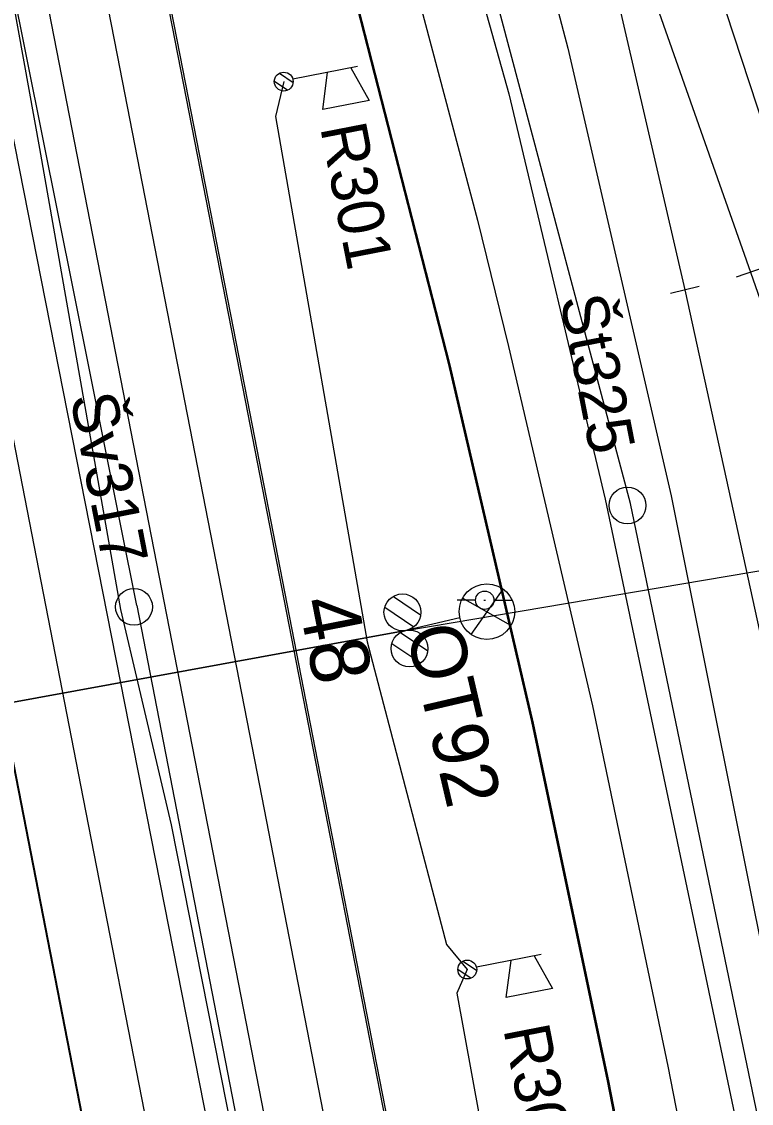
# Model space of a CAD drawing. Extents: x -545736 to -544888, y -1122892 to -1119128.
# Drawn here: x -545228.83 to -545209.03, y -1121674.47 to -1121645.11 of the extents above; entities that cross this region are included whole.
import ezdxf

# ---------------------------------------------------------------- set-up
doc = ezdxf.new("R2010")
doc.units = 0
for name, color, linetype in [('Podbarveni_Nastupiste', 7, 'Continuous'), ('Vrstva 1 - Koleje', 7, 'Continuous'), ('Vrstva 11 - Trakce', 7, 'Continuous'), ('Vrstva 14_zastreseni a nastupiste', 7, 'Continuous'), ('Vrstva 16_plochy', 7, 'Continuous'), ('Vrstva 2 - Vyhybky', 7, 'Continuous'), ('Vrstva 25', 7, 'Continuous'), ('Vrstva 28 - zabzar', 7, 'Continuous'), ('Vrstva 31', 7, 'Continuous'), ('Vrstva 33 - prvky sdelzar', 7, 'Continuous'), ('Vrstva 4 - Teren - stezky - prechody - plochy', 7, 'Continuous'), ('Vrstva 41', 7, 'Continuous'), ('Vrstva 43', 7, 'Continuous'), ('Vrstva 44', 7, 'Continuous')]:
    doc.layers.add(name, color=color, linetype=linetype)

msp = doc.modelspace()

# ---------------------------------------------------------------- linework, layer by layer
at = {"layer": 'Podbarveni_Nastupiste'}
for points in [[(-545223.443, -1121694.09), (-545224.969, -1121686.265), (-545226.877, -1121676.484), (-545228.786, -1121666.678), (-545230.697, -1121656.879), (-545232.606, -1121647.081), (-545234.517, -1121637.287), (-545236.429, -1121627.481), (-545237.19, -1121623.577)], [(-545209.127, -1121693.444), (-545211.033, -1121683.652), (-545212.936, -1121673.863), (-545214.985, -1121664.112), (-545217.251, -1121654.384), (-545219.728, -1121644.713), (-545222.418, -1121635.111), (-545225.09, -1121625.931)], [(-545228.364, -1121626.398), (-545228.067, -1121627.952), (-545226.537, -1121635.795), (-545224.621, -1121645.607), (-545222.714, -1121655.377), (-545220.803, -1121665.19), (-545219.276, -1121673.043), (-545217.368, -1121682.822), (-545215.446, -1121692.657)]]:
    msp.add_lwpolyline(points, dxfattribs=at)
at = {"layer": 'Vrstva 1 - Koleje'}
for points in [[(-545253.234, -1121532.442), (-545253.081, -1121533.227), (-545252.417, -1121536.637), (-545250.056, -1121548.75), (-545246.877, -1121565.063), (-545245.498, -1121572.114), (-545243.946, -1121580.081), (-545242.319, -1121588.422), (-545241.158, -1121594.375), (-545240.981, -1121595.287), (-545240.164, -1121599.483), (-545238.848, -1121606.232), (-545237.423, -1121613.54), (-545235.54, -1121623.195), (-545234.061, -1121630.792), (-545232.534, -1121638.617), (-545230.963, -1121646.68), (-545229.074, -1121656.39), (-545227.16, -1121666.203), (-545225.219, -1121676.178), (-545223.305, -1121685.999), (-545221.784, -1121693.786)], [(-545248.408, -1121532.36), (-545248.259, -1121533.126), (-545247.475, -1121537.15), (-545244.429, -1121552.772), (-545240.225, -1121574.335), (-545238.879, -1121581.23), (-545237.501, -1121588.285), (-545235.953, -1121596.229), (-545234.349, -1121604.465), (-545232.932, -1121611.716), (-545232.152, -1121615.725), (-545231.632, -1121618.395), (-545230.091, -1121626.302), (-545228.735, -1121633.259), (-545226.244, -1121646.023), (-545224.344, -1121655.776), (-545222.446, -1121665.521), (-545220.908, -1121673.435), (-545219.01, -1121683.169), (-545217.101, -1121692.961)], [(-545225.616, -1121618.075), (-545225.108, -1121619.818), (-545223.546, -1121625.178), (-545221.373, -1121632.649), (-545218.975, -1121641.029), (-545216.466, -1121650.504), (-545215.616, -1121653.926), (-545213.339, -1121663.68), (-545211.292, -1121673.464), (-545209.393, -1121683.199), (-545207.488, -1121692.987)], [(-545219.417, -1121620.337), (-545219.184, -1121621.102), (-545214.573, -1121636.23), (-545210.836, -1121652.388), (-545208.739, -1121661.984), (-545207.134, -1121670.028), (-545205.963, -1121676.033), (-545204.911, -1121681.437), (-545204.598, -1121683.045), (-545202.446, -1121694.084)], [(-545219.417, -1121620.337), (-545219.184, -1121621.102), (-545214.573, -1121636.23), (-545209.054, -1121651.908), (-545206.51, -1121659.176), (-545203.144, -1121668.78), (-545201.044, -1121674.823), (-545198.261, -1121683.246), (-545197.623, -1121685.281), (-545196.328, -1121689.408), (-545194.686, -1121694.87)]]:
    msp.add_lwpolyline(points, dxfattribs=at)
at = {"layer": 'Vrstva 11 - Trakce'}
for p, q in [((-545218.746, -1121660.712), (-545218.005, -1121661.209)), ((-545218.977, -1121661.008), (-545218.19, -1121661.537)), ((-545218.555, -1121661.696), (-545217.812, -1121662.194)), ((-545218.785, -1121661.994), (-545217.999, -1121662.52))]:
    msp.add_line(p, q, dxfattribs=at)
msp.add_lwpolyline([(-545232.384, -1121664.189), (-545218.403, -1121661.636), (-545207.172, -1121659.74)], dxfattribs=at)
for centre in [(-545218.5, -1121661.145), (-545218.306, -1121662.127)]:
    msp.add_circle(centre, 0.5, dxfattribs=at)
at = {"layer": 'Vrstva 14_zastreseni a nastupiste'}
for points in [[(-545223.426, -1121694.08), (-545224.952, -1121686.255), (-545226.86, -1121676.474), (-545228.769, -1121666.668), (-545230.68, -1121656.869), (-545232.589, -1121647.071), (-545234.5, -1121637.277), (-545236.412, -1121627.471), (-545237.19, -1121623.577), (-545242.618, -1121624.735)], [(-545223.443, -1121694.09), (-545224.969, -1121686.265), (-545226.877, -1121676.484), (-545228.786, -1121666.678), (-545230.697, -1121656.879), (-545232.606, -1121647.081), (-545234.517, -1121637.287), (-545236.429, -1121627.481), (-545237.19, -1121623.577)], [(-545225.09, -1121625.931), (-545225.09, -1121625.931), (-545228.364, -1121626.398), (-545228.364, -1121626.398), (-545228.12, -1121627.967), (-545226.59, -1121635.81), (-545224.674, -1121645.622), (-545222.767, -1121655.392), (-545220.856, -1121665.205), (-545219.329, -1121673.058), (-545217.421, -1121682.837), (-545215.499, -1121692.672)], [(-545209.083, -1121693.488), (-545210.989, -1121683.696), (-545212.892, -1121673.907), (-545214.941, -1121664.156), (-545217.207, -1121654.428), (-545219.684, -1121644.757), (-545222.374, -1121635.155), (-545225.09, -1121625.931), (-545228.364, -1121626.398)], [(-545209.127, -1121693.444), (-545211.033, -1121683.652), (-545212.936, -1121673.863), (-545214.985, -1121664.112), (-545217.251, -1121654.384), (-545219.728, -1121644.713), (-545222.418, -1121635.111), (-545225.09, -1121625.931)], [(-545228.364, -1121626.398), (-545228.067, -1121627.952), (-545226.537, -1121635.795), (-545224.621, -1121645.607), (-545222.714, -1121655.377), (-545220.803, -1121665.19), (-545219.276, -1121673.043), (-545217.368, -1121682.822), (-545215.446, -1121692.657)]]:
    msp.add_lwpolyline(points, dxfattribs=at)
at = {"layer": 'Vrstva 16_plochy'}
for points in [[(-545223.443, -1121694.09), (-545224.969, -1121686.265), (-545226.877, -1121676.484), (-545228.786, -1121666.678), (-545230.697, -1121656.879), (-545232.606, -1121647.081), (-545234.517, -1121637.287), (-545236.429, -1121627.481), (-545237.19, -1121623.577), (-545242.618, -1121624.735)], [(-545209.127, -1121693.444), (-545211.033, -1121683.652), (-545212.936, -1121673.863), (-545214.985, -1121664.112), (-545217.251, -1121654.384), (-545219.728, -1121644.713), (-545222.418, -1121635.111), (-545225.09, -1121625.931), (-545228.364, -1121626.398)], [(-545228.364, -1121626.398), (-545228.067, -1121627.952), (-545226.537, -1121635.795), (-545224.621, -1121645.607), (-545222.714, -1121655.377), (-545220.803, -1121665.19), (-545219.276, -1121673.043), (-545217.368, -1121682.822), (-545215.446, -1121692.657)]]:
    msp.add_lwpolyline(points, dxfattribs=at)
at = {"layer": 'Vrstva 2 - Vyhybky'}
for p, q in [((-545209.432, -1121652.04), (-545208.676, -1121651.776)), ((-545211.225, -1121652.481), (-545210.447, -1121652.295))]:
    msp.add_line(p, q, dxfattribs=at)
for points in [[(-545219.417, -1121620.337), (-545219.184, -1121621.102), (-545214.573, -1121636.23), (-545209.054, -1121651.908)], [(-545214.573, -1121636.23), (-545210.836, -1121652.388)]]:
    msp.add_lwpolyline(points, dxfattribs=at)
at = {"layer": 'Vrstva 25'}
for p, q in [((-545215.555, -1121661.504), (-545216.867, -1121660.76)), ((-545215.771, -1121660.512), (-545216.639, -1121661.744)), ((-545216.942, -1121661.295), (-545218.403, -1121661.636))]:
    msp.add_line(p, q, dxfattribs=at)
msp.add_lwpolyline([(-545218.403, -1121661.636), (-545232.384, -1121664.189)], dxfattribs=at)
msp.add_circle((-545216.207, -1121661.126), 0.754, dxfattribs=at)
at = {"layer": 'Vrstva 28 - zabzar'}
msp.add_lwpolyline([(-545222.23, -1121715.29), (-545222.21, -1121715.31), (-545221.11, -1121715.76), (-545219.32, -1121715.69), (-545215.16, -1121714.7), (-545215.49, -1121713.47), (-545218.48, -1121699.21), (-545219.11, -1121698), (-545219.09, -1121695.58), (-545224.77, -1121666.91), (-545226.14, -1121661.07), (-545228.34, -1121648.56), (-545231.24, -1121632.53), (-545233.58, -1121619.99), (-545234.02, -1121617.79), (-545229.44, -1121616.68)], dxfattribs=at)
at = {"layer": 'Vrstva 31'}
msp.add_lwpolyline([(-545221.72, -1121646.74), (-545221.94, -1121647.69), (-545219.46, -1121661.95), (-545217.3, -1121670.16), (-545216.74, -1121670.84), (-545217.02, -1121671.48), (-545214.35, -1121686.1), (-545212.39, -1121694.8), (-545212.08, -1121695.18), (-545212.1, -1121695.77), (-545212.36, -1121697.88), (-545211.9, -1121700.18), (-545210.85, -1121702.71), (-545209.44, -1121709.64), (-545207.97, -1121711.94), (-545208.32, -1121712.72)], dxfattribs=at)
at = {"layer": 'Vrstva 33 - prvky sdelzar'}
for p, q in [((-545219.716, -1121646.332), (-545221.472, -1121646.677)), ((-545219.904, -1121646.369), (-545219.406, -1121647.25)), ((-545221.836, -1121646.512), (-545221.467, -1121646.761)), ((-545220.662, -1121647.495), (-545220.532, -1121646.491)), ((-545221.975, -1121646.728), (-545221.613, -1121646.971)), ((-545219.406, -1121647.25), (-545220.662, -1121647.495)), ((-545214.735, -1121670.433), (-545216.492, -1121670.777)), ((-545214.924, -1121670.47), (-545214.426, -1121671.351)), ((-545216.856, -1121670.612), (-545216.487, -1121670.861)), ((-545215.683, -1121671.595), (-545215.552, -1121670.592)), ((-545216.995, -1121670.828), (-545216.633, -1121671.072)), ((-545214.426, -1121671.351), (-545215.683, -1121671.595))]:
    msp.add_line(p, q, dxfattribs=at)
for centre in [(-545221.72, -1121646.74), (-545216.74, -1121670.84)]:
    msp.add_circle(centre, 0.256, dxfattribs=at)
at = {"layer": 'Vrstva 4 - Teren - stezky - prechody - plochy'}
for points in [[(-545191.805, -1121699.137), (-545194.474, -1121690.403), (-545196.452, -1121683.768), (-545199.249, -1121675.317), (-545202.803, -1121664.861), (-545207.816, -1121650.626), (-545217.94, -1121619.813), (-545226.341, -1121592.264), (-545232.146, -1121573.195), (-545235.937, -1121558.858), (-545238.806, -1121546.877), (-545241.095, -1121537.02)], [(-545230.058, -1121593.624), (-545229.255, -1121593.407), (-545223.205, -1121613.276), (-545220.476, -1121622.38), (-545217.216, -1121633.69), (-545214.01, -1121645.83), (-545211.204, -1121657.98), (-545206.59, -1121681.008), (-545202.547, -1121701.925)], [(-545230.058, -1121593.624), (-545227.825, -1121603.756), (-545225.054, -1121614.151), (-545222.526, -1121623.034), (-545219.417, -1121633.474), (-545215.613, -1121647.074), (-545212.994, -1121658.069), (-545207.784, -1121682.857), (-545204.102, -1121702.263)], [(-545157.45, -1122022.175), (-545154.783, -1122021.634), (-545154.868, -1122020.873), (-545158.409, -1122002.766), (-545161.985, -1121984.181), (-545167.947, -1121953.502), (-545173.012, -1121927.482), (-545183.259, -1121874.859), (-545192.216, -1121829.241), (-545202.384, -1121776.657), (-545211.092, -1121732.141), (-545220.696, -1121682.724), (-545230.205, -1121633.983), (-545237.607, -1121595.717), (-545239.248, -1121596.014)], [(-545157.45, -1122022.175), (-545157.217, -1122021.677), (-545160.795, -1122002.888), (-545164.002, -1121984.847), (-545169.404, -1121955.723), (-545174.573, -1121927.833), (-545184.757, -1121874.943), (-545193.65, -1121829.68), (-545203.839, -1121777.07), (-545212.63, -1121732.332), (-545221.738, -1121685.421), (-545231.797, -1121634.381), (-545239.248, -1121596.014)], [(-545223.426, -1121694.08), (-545224.952, -1121686.255), (-545226.86, -1121676.474), (-545228.769, -1121666.668), (-545230.68, -1121656.869), (-545232.589, -1121647.071), (-545234.5, -1121637.277), (-545236.412, -1121627.471), (-545237.19, -1121623.577), (-545237.268, -1121623.173), (-545239.142, -1121623.538), (-545239.467, -1121621.819), (-545241.173, -1121622.164), (-545240.881, -1121623.876), (-545242.686, -1121624.268), (-545242.618, -1121624.735), (-545241.193, -1121634.528), (-545239.4, -1121644.342), (-545237.499, -1121654.105), (-545235.587, -1121663.905), (-545233.679, -1121673.704), (-545231.771, -1121683.482), (-545229.851, -1121693.331)], [(-545209.083, -1121693.488), (-545210.989, -1121683.696), (-545212.892, -1121673.907), (-545214.941, -1121664.156), (-545217.207, -1121654.428), (-545219.684, -1121644.757), (-545222.374, -1121635.155), (-545225.09, -1121625.931), (-545225.208, -1121625.521), (-545228.442, -1121626.001), (-545228.364, -1121626.398), (-545228.12, -1121627.967), (-545226.59, -1121635.81), (-545224.674, -1121645.622), (-545222.767, -1121655.392), (-545220.856, -1121665.205), (-545219.329, -1121673.058), (-545217.421, -1121682.837), (-545215.499, -1121692.672)]]:
    msp.add_lwpolyline(points, dxfattribs=at)
at = {"layer": 'Vrstva 41'}
for p, q in [((-545216.516, -1121660.817), (-545217.016, -1121660.817)), ((-545216.291, -1121660.817), (-545216.241, -1121660.817)), ((-545216.016, -1121660.817), (-545215.516, -1121660.817))]:
    msp.add_line(p, q, dxfattribs=at)
msp.add_circle((-545216.266, -1121660.817), 0.25, dxfattribs=at)
at = {"layer": 'Vrstva 43'}
for centre in [(-545212.391, -1121658.244), (-545225.784, -1121660.996)]:
    msp.add_circle(centre, 0.5, dxfattribs=at)
at = {"layer": 'Vrstva 44'}
for points in [[(-545203.565, -1121700.334), (-545212.31, -1121658.192), (-545222.869, -1121618.503), (-545222.832, -1121618.218)], [(-545225.704, -1121660.962), (-545233.807, -1121620.679), (-545233.724, -1121620.432)], [(-545225.704, -1121660.962), (-545218.502, -1121698.049), (-545211.321, -1121734.873), (-545211.203, -1121735.259)]]:
    msp.add_lwpolyline(points, dxfattribs=at)

# ---------------------------------------------------------------- texts
at = {"layer": 'Vrstva 11 - Trakce'}
msp.add_text('48', height=1.6, rotation=281.1622, dxfattribs=at).set_placement((-545221.33, -1121660.851))
at = {"layer": 'Vrstva 25'}
msp.add_text('OT92', height=1.5, rotation=283.14, dxfattribs=at).set_placement((-545218.403, -1121661.636))
at = {"layer": 'Vrstva 33 - prvky sdelzar'}
for s, rotation, p in [('R301', 281.0403, (-545220.735, -1121647.983)), ('R302', 281.0121, (-545215.764, -1121672.456))]:
    msp.add_text(s, height=1.25, rotation=rotation, dxfattribs=at).set_placement(p)
at = {"layer": 'Vrstva 43'}
for s, p in [('Št325', (-545214.226, -1121652.63)), ('Šv317', (-545227.521, -1121655.298))]:
    msp.add_text(s, height=1.25, rotation=281.0323, dxfattribs=at).set_placement(p)

doc.saveas('drawing.dxf')
